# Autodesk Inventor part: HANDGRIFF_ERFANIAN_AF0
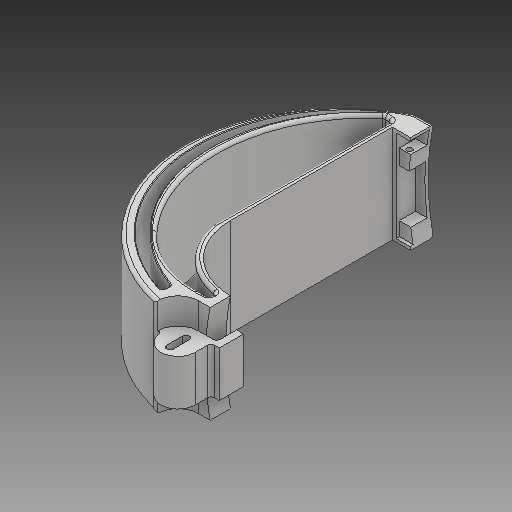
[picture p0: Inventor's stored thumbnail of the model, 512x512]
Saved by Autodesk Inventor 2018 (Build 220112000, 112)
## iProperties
Created: 2019-01
Part Number: HANDGRIFF_ERFANIAN_AF0
Material: Polypropylene (PP)
Document SubType Name: Modeling
Designer: zand
Density: 0.902188 g/cm^3
Appearance: Vorgabe
Mass: 18.6223 g
Surface Area: 207.812 cm^2
Volume: 20.6413 cm^3
Author: zand
Revision Number: 19LAST_VERSION
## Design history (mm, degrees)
feature "Basis1"
node "Volumenkörper1"
